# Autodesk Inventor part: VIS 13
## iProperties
Created: 2004-11
Part Number: VIS 13
Document SubType Name: Modeling
Designer: Bruno
Manufacturer: Standard
Standards Organization: Custom
Author: Bruno
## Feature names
1. Base1
